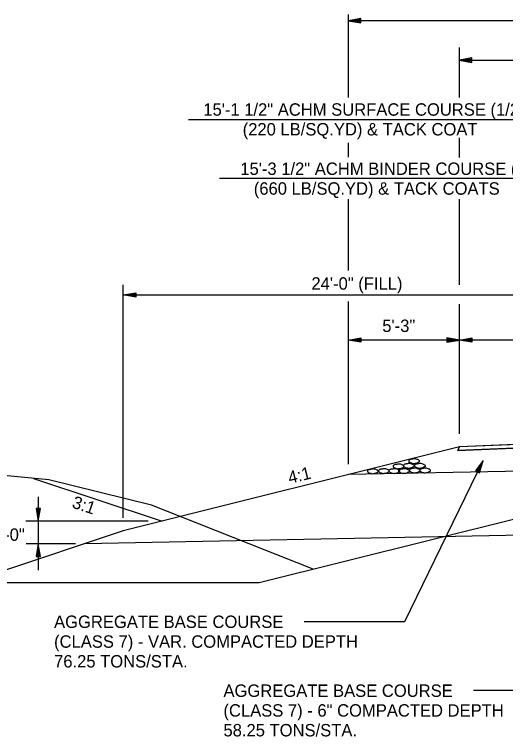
# Model space of a CAD drawing. Extents: x 1398565 to 1398920, y 1968324 to 1968581.
# Drawn here: x 1398599.68 to 1398623.06, y 1968542.62 to 1968576.97 of the extents above; entities that cross this region are included whole.
import ezdxf

# ---------------------------------------------------------------- set-up
doc = ezdxf.new("R2010")
doc.units = 0
for name, color, linetype in [('1', 7, 'Continuous'), ('10', 7, 'Continuous'), ('19', 7, 'Continuous'), ('42', 7, 'Continuous'), ('Default', 7, 'Continuous')]:
    doc.layers.add(name, color=color, linetype=linetype)

# ---------------------------------------------------------------- blocks, each defined once
blk = doc.blocks.new('ROCKS')
at = {"layer": '1'}
blk.add_spline([(0.013, 0.06), (0.053, 0.053), (0.107, 0.033), (0.133, 0.013), (0.133, -0.007), (0.12, -0.033), (0.107, -0.04), (0.073, -0.053), (0.033, -0.067), (0.013, -0.067), (-0.02, -0.06), (-0.06, -0.053), (-0.087, -0.047), (-0.113, -0.02), (-0.113, -0.007), (-0.107, 0.02), (-0.087, 0.033), (-0.067, 0.047), (-0.033, 0.053), (-0.02, 0.06), (0.013, 0.06)], degree=3, dxfattribs=at)
blk = doc.blocks.new('4TO1 ABC')
at = {"layer": '1', "xscale": 0.1312491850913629, "yscale": 0.1312491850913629, "rotation": 180}
for p in [(0.00175, -0.00875), (-0.016625, -0.023625), (0.018375, -0.023625), (0.051625, -0.025375), (-0.03325, -0.0385), (0, -0.0385), (0.034125, -0.04025), (0.06475, -0.04025), (0.098, -0.04025), (0.133, -0.041125)]:
    blk.add_blockref('ROCKS', p, dxfattribs=at)

msp = doc.modelspace()

# ---------------------------------------------------------------- linework, layer by layer
at = {"layer": '19'}
for p, q in [((1398615.574, 1968573.027), (1398615.574, 1968576.974)), ((1398616.174, 1968576.781), (1398615.574, 1968576.676)), ((1398641.859, 1968576.676), (1398615.574, 1968576.676)), ((1398615.574, 1968576.676), (1398616.174, 1968576.571)), ((1398616.174, 1968576.726), (1398615.734, 1968576.691)), ((1398615.734, 1968576.661), (1398616.174, 1968576.621)), ((1398616.174, 1968576.571), (1398616.174, 1968576.781)), ((1398620.859, 1968573.027), (1398620.859, 1968575.401)), ((1398621.459, 1968574.906), (1398620.859, 1968574.801)), ((1398621.459, 1968574.696), (1398621.459, 1968574.906)), ((1398620.859, 1968574.801), (1398660.859, 1968574.801)), ((1398620.859, 1968574.801), (1398621.459, 1968574.696)), ((1398621.459, 1968574.851), (1398621.019, 1968574.816)), ((1398621.019, 1968574.786), (1398621.459, 1968574.746)), ((1398607.966, 1968571.979), (1398641.859, 1968571.979)), ((1398620.859, 1968570.162), (1398620.859, 1968571.099)), ((1398615.574, 1968570.18), (1398615.574, 1968570.869)), ((1398609.436, 1968569.181), (1398641.859, 1968569.181)), ((1398615.574, 1968564.786), (1398615.574, 1968568.182)), ((1398620.859, 1968564.104), (1398620.859, 1968568.182)), ((1398604.859, 1968563.63), (1398605.459, 1968563.735)), ((1398604.859, 1968563.63), (1398628.859, 1968563.63)), ((1398605.459, 1968563.525), (1398604.859, 1968563.63)), ((1398605.019, 1968563.645), (1398605.459, 1968563.68)), ((1398605.459, 1968563.575), (1398605.019, 1968563.615)), ((1398605.459, 1968563.735), (1398605.459, 1968563.525)), ((1398615.574, 1968555.582), (1398615.574, 1968563.319)), ((1398620.859, 1968557.02), (1398620.859, 1968563.195)), ((1398615.574, 1968561.485), (1398616.174, 1968561.59)), ((1398640.859, 1968561.485), (1398615.574, 1968561.485)), ((1398616.174, 1968561.38), (1398615.574, 1968561.485)), ((1398615.734, 1968561.5), (1398616.174, 1968561.535)), ((1398616.174, 1968561.59), (1398616.174, 1968561.38)), ((1398620.259, 1968561.59), (1398620.259, 1968561.38)), ((1398620.859, 1968561.485), (1398620.259, 1968561.59)), ((1398620.699, 1968561.5), (1398620.259, 1968561.535)), ((1398620.259, 1968561.38), (1398620.859, 1968561.485)), ((1398620.859, 1968561.485), (1398621.459, 1968561.59)), ((1398621.459, 1968561.38), (1398620.859, 1968561.485)), ((1398621.019, 1968561.5), (1398621.459, 1968561.535)), ((1398621.459, 1968561.59), (1398621.459, 1968561.38)), ((1398616.174, 1968561.43), (1398615.734, 1968561.47)), ((1398620.259, 1968561.43), (1398620.699, 1968561.47)), ((1398621.459, 1968561.43), (1398621.019, 1968561.47)), ((1398620.859, 1968556.402), (1398604.859, 1968552.402)), ((1398626.859, 1968556.475), (1398620.774, 1968556.232)), ((1398620.859, 1968556.402), (1398620.774, 1968556.232)), ((1398626.859, 1968556.642), (1398620.859, 1968556.402)), ((1398618.268, 1968548.089), (1398621.996, 1968555.747)), ((1398621.996, 1968555.747), (1398621.632, 1968555.258)), ((1398621.819, 1968555.166), (1398621.996, 1968555.747)), ((1398640.859, 1968555.586), (1398615.574, 1968555.08)), ((1398621.913, 1968555.611), (1398621.681, 1968555.237)), ((1398621.775, 1968555.189), (1398621.938, 1968555.598)), ((1398621.632, 1968555.258), (1398621.819, 1968555.166)), ((1398600.59, 1968554.901), (1398606.704, 1968552.863)), ((1398600.814, 1968554.021), (1398600.814, 1968552.745)), ((1398600.919, 1968553.463), (1398600.709, 1968553.463)), ((1398600.709, 1968553.463), (1398600.814, 1968552.863)), ((1398600.764, 1968553.463), (1398600.799, 1968553.023)), ((1398600.814, 1968552.863), (1398600.919, 1968553.463)), ((1398600.829, 1968553.023), (1398600.869, 1968553.463)), ((1398600.814, 1968552.745), (1398600.814, 1968550.539)), ((1398641.859, 1968552.566), (1398603.022, 1968551.789)), ((1398604.859, 1968552.402), (1398597.492, 1968549.946)), ((1398600.814, 1968551.789), (1398600.709, 1968551.189)), ((1398600.799, 1968551.629), (1398600.764, 1968551.189)), ((1398600.919, 1968551.189), (1398600.814, 1968551.789)), ((1398600.869, 1968551.189), (1398600.829, 1968551.629)), ((1398600.709, 1968551.189), (1398600.919, 1968551.189)), ((1398613.47, 1968548.089), (1398618.268, 1968548.089)), ((1398621.539, 1968544.829), (1398625.067, 1968544.829))]:
    msp.add_line(p, q, dxfattribs=at)
msp.add_lwpolyline([(1398620.777, 1968556.237), (1398626.859, 1968556.475), (1398640.859, 1968556.755), (1398654.859, 1968556.475), (1398660.944, 1968556.232), (1398660.859, 1968556.402), (1398654.859, 1968556.642), (1398640.859, 1968556.922), (1398626.859, 1968556.642), (1398620.859, 1968556.402)], close=True, dxfattribs=at)
at = {"layer": '42'}
for points in [[(1398613.903, 1968550.586), (1398606.201, 1968553.623), (1398601.314, 1968554.831), (1398595.7, 1968555.373), (1398584.241, 1968556.087), (1398566.939, 1968556.681)], [(1398564.837, 1968549.946), (1398611.333, 1968549.946), (1398635.859, 1968556.055), (1398641.859, 1968556.295)], [(1398564.837, 1968549.946), (1398610.787, 1968549.946)]]:
    msp.add_lwpolyline(points, dxfattribs=at)
at = {"layer": 'Default'}
for p, q in [((1398604.859, 1968553.018), (1398604.859, 1968564.104)), ((1398606.042, 1968552.863), (1398600.219, 1968552.863)), ((1398602.585, 1968551.789), (1398600.233, 1968551.789))]:
    msp.add_line(p, q, dxfattribs=at)

# ---------------------------------------------------------------- block references
at = {"layer": '19', "xscale": 14.999970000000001, "yscale": -14.999970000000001, "rotation": 180}
msp.add_blockref('4TO1 ABC', (1398618.714, 1968555.849), dxfattribs=at)

# ---------------------------------------------------------------- texts
at = {"layer": '10'}
for s, height, rotation, p in [('24\'-0" (FILL)', 0.59001, 360, (1398613.818, 1968563.881)), ('5\'-3"', 0.59, 360, (1398617.191, 1968561.868)), ('4:1', 0.59, 13.7364, (1398612.78, 1968554.639)), ('3:1', 0.59, 341.5224, (1398602.378, 1968553.525)), ('1\'-0"', 0.59, 360, (1398598.599, 1968551.932))]:
    msp.add_text(s, height=height, rotation=rotation, dxfattribs=at).set_placement(p)
at = {"layer": '19'}
for s, p in [('AGGREGATE BASE COURSE', (1398601.565, 1968547.786)), ('(CLASS 7) - VAR. COMPACTED DEPTH', (1398601.565, 1968546.846)), ('76.25 TONS/STA.', (1398601.565, 1968545.906)), ('AGGREGATE BASE COURSE', (1398609.629, 1968544.508)), ('(CLASS 7) - 6" COMPACTED DEPTH', (1398609.629, 1968543.568)), ('58.25 TONS/STA.', (1398609.629, 1968542.628))]:
    msp.add_text(s, height=0.59001, rotation=360, dxfattribs=at).set_placement(p)
at = {"layer": '42'}
for s, p in [('15\'-1 1/2" ACHM SURFACE COURSE (1/2")', (1398608.67, 1968572.157)), ('(220 LB/SQ.YD) & TACK COAT', (1398610.544, 1968571.217)), ('15\'-3 1/2" ACHM BINDER COURSE (1")', (1398610.432, 1968569.339)), ('(660 LB/SQ.YD) & TACK COATS', (1398611.073, 1968568.399))]:
    msp.add_text(s, height=0.59001, rotation=360, dxfattribs=at).set_placement(p)

doc.saveas('drawing.dxf')
